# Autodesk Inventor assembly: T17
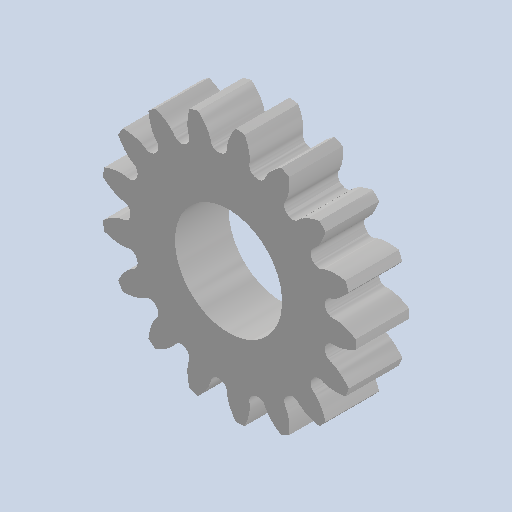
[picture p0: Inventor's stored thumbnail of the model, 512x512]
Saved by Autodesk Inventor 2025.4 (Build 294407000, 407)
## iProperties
Created: 2026-05
Part Number: T17
Document SubType Name: Assembly
Designer: AdminForWorker
Title: T17 v1
Author: AdminForWorker
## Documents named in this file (2)
- c:\worker\convert-fusion-r03-cosv3\tmp\job-1\34\temp\files\4fc3af46-4beb-42d9-b68e-1a89435d35d9\22886be9-a611-4735-baff-75cd805b2610.iam
- c:\worker\convert-fusion-r03-cosv3\tmp\job-1\34\temp\files\4fc3af46-4beb-42d9-b68e-1a89435d35d9\Spur Gear 17 teeth.ipt
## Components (1 placed, 1 different names)
1. Spur Gear 17 teeth:1
